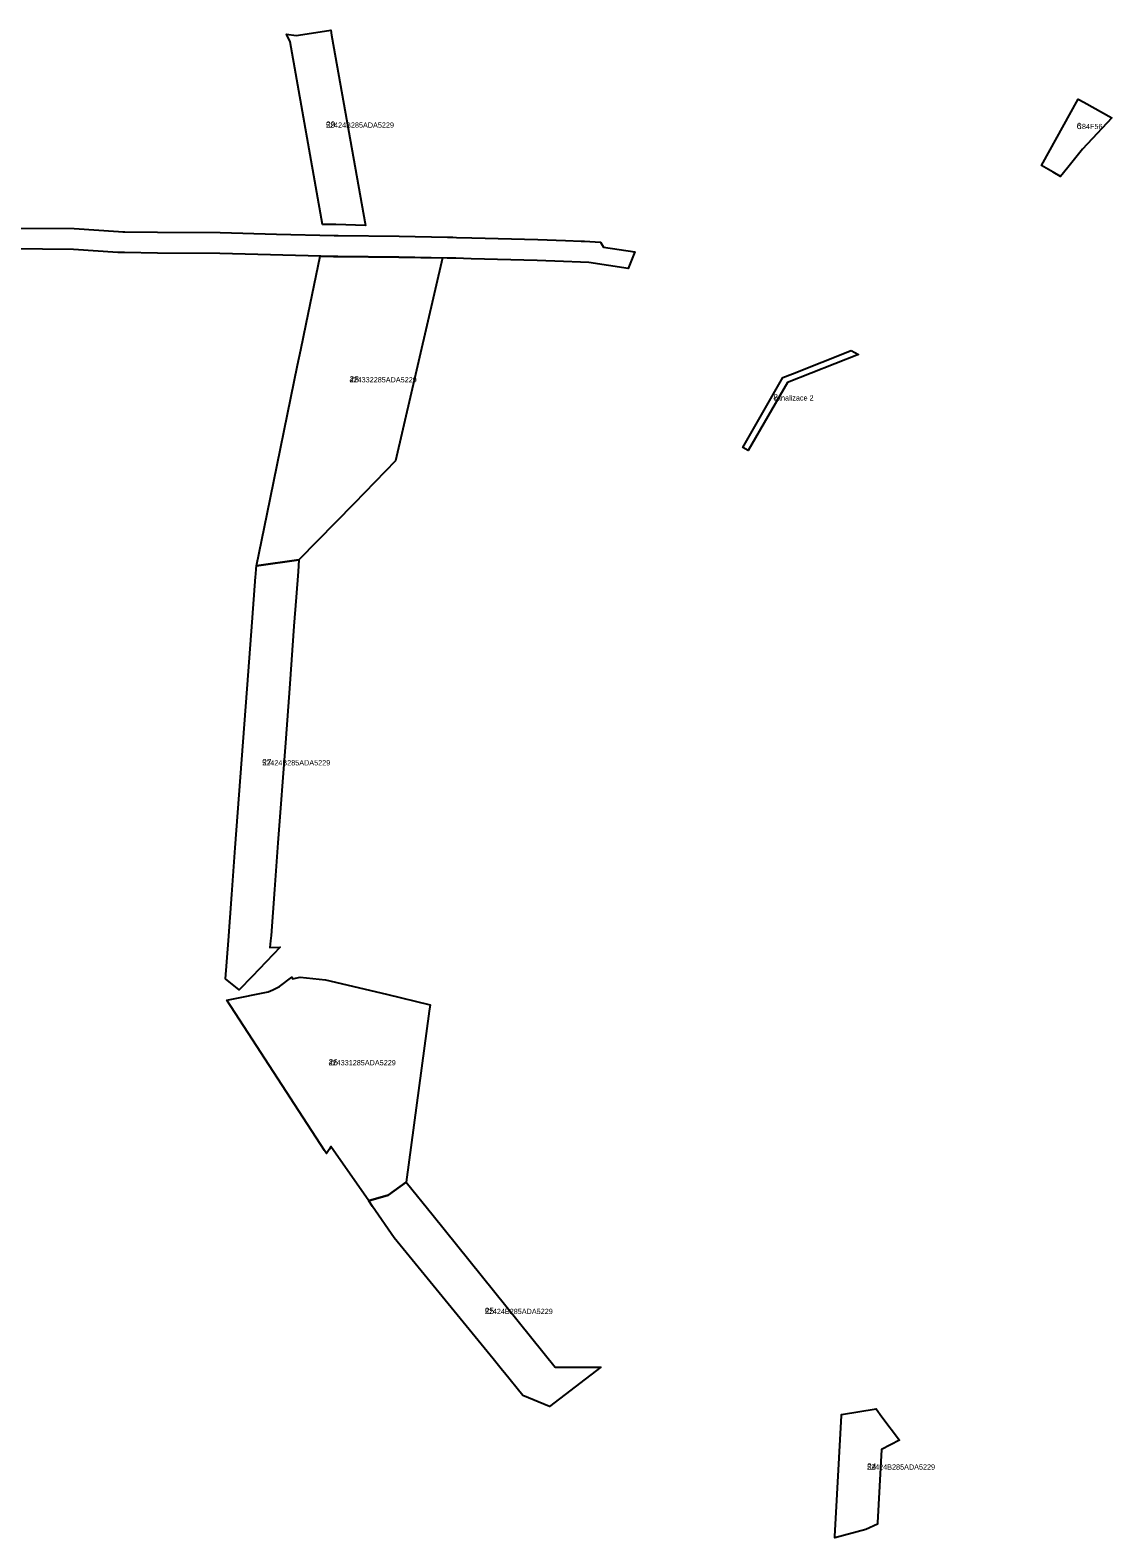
# Model space of a CAD drawing. Extents: x -540086 to -538022, y -1162553 to -1159940.
# Drawn here: x -539054 to -538022, y -1162553 to -1161115 of the extents above; entities that cross this region are included whole.
import ezdxf

# ---------------------------------------------------------------- set-up
doc = ezdxf.new("R2010")
doc.units = 0
for name, color, linetype in [('96120023', 7, 'Continuous'), ('96140023', 7, 'Continuous'), ('ID_VPO', 7, 'Continuous'), ('ID_VPS', 7, 'Continuous')]:
    doc.layers.add(name, color=color, linetype=linetype)

msp = doc.modelspace()

# ---------------------------------------------------------------- linework, layer by layer
at = {"layer": '96120023'}
for points in [[(-538063.9, -1161245.9), (-538070.9, -1161254.5), (-538078.1, -1161250.3), (-538089, -1161244.1), (-538054.2, -1161180.6), (-538048.7, -1161183.6), (-538022, -1161198.5), (-538049.9, -1161228.5)], [(-538270.8, -1161420.6), (-538263.8, -1161424.2), (-538331.5, -1161451), (-538368.8, -1161515.9), (-538374, -1161512.9), (-538335.7, -1161446.2), (-538335.7, -1161446.2), (-538326.7, -1161442.6)]]:
    msp.add_lwpolyline(points, close=True, dxfattribs=at)
msp.add_lwpolyline([(-539073, -1161303.6), (-539011.9, -1161304.2), (-538969.5, -1161307), (-538965.6, -1161307.1), (-538963.6, -1161307.1), (-538932.3, -1161307.5), (-538872.6, -1161308), (-538818.8, -1161309.4), (-538763.9, -1161310.7), (-538759.9, -1161310.9), (-538702, -1161311.5), (-538655.9, -1161312.3), (-538650.6, -1161312.4), (-538647.1, -1161312.5), (-538632.6, -1161312.9), (-538569.5, -1161314.7), (-538543.2, -1161315.4), (-538528.1, -1161316.2), (-538525.1, -1161316.3), (-538509.9, -1161317), (-538506.8, -1161321.8), (-538477.1, -1161326.2), (-538483.5, -1161342.2), (-538521, -1161336.5), (-538529, -1161336.1), (-538545, -1161335.4), (-538570.1, -1161334.7), (-538633.2, -1161332.9), (-538647.7, -1161332.5), (-538656.2, -1161332.3), (-538702.3, -1161331.5), (-538760.4, -1161330.8), (-538764.6, -1161330.7), (-538872.9, -1161328), (-538932.5, -1161327.5), (-538963.9, -1161327.1), (-538970.4, -1161327), (-539012.7, -1161324.2), (-539071.6, -1161323.6)], dxfattribs=at)
at = {"layer": '96140023'}
for points in [[(-538762.2, -1161300.4), (-538775, -1161300.2), (-538805.7, -1161126), (-538809.4, -1161118.5), (-538800.1, -1161120), (-538777.3, -1161116.4), (-538767.2, -1161114.8), (-538766.4, -1161119.7), (-538734, -1161301.3)], [(-538838, -1161625.8), (-538827.8, -1161576.4), (-538798.7, -1161434.4), (-538795.7, -1161419.9), (-538790.6, -1161394.9), (-538777.3, -1161330.4), (-538764.6, -1161330.7), (-538760.4, -1161330.8), (-538702.3, -1161331.5), (-538660.5, -1161332.2), (-538705.3, -1161525.9), (-538744.9, -1161566.5), (-538797.5, -1161620.3)], [(-538838.2, -1161628.7), (-538838, -1161625.8), (-538797.5, -1161620.3), (-538798.3, -1161631.5), (-538800.1, -1161655.9), (-538802.2, -1161683.6), (-538806.3, -1161738.5), (-538810.4, -1161794.8), (-538817.5, -1161890.2), (-538820.8, -1161934.9), (-538824.1, -1161978.8), (-538824.5, -1161983.9), (-538825.3, -1161990.1), (-538815.4, -1161989.8), (-538842, -1162017.7), (-538854.4, -1162030.6), (-538867.5, -1162019.9), (-538864.8, -1161983.6), (-538861.5, -1161939.7), (-538858.2, -1161895), (-538846.8, -1161743.2), (-538842.7, -1161688.3), (-538838.8, -1161636.3), (-538838.6, -1161634)], [(-538713.9, -1162034.8), (-538672.3, -1162044.8), (-538673.1, -1162051), (-538695.1, -1162214.1), (-538712.3, -1162226.5), (-538729, -1162231.4), (-538730.9, -1162232), (-538766.9, -1162179.9), (-538768.8, -1162182.8), (-538771.3, -1162186.7), (-538773.1, -1162183.9), (-538866.2, -1162040.4), (-538863.1, -1162039.8), (-538826.9, -1162032.5), (-538822.4, -1162030.5), (-538816, -1162027.5), (-538804.3, -1162018.4), (-538803.6, -1162020.1), (-538796.4, -1162018.5), (-538772, -1162020.9)], [(-538730.9, -1162232), (-538729, -1162231.4), (-538712.3, -1162226.5), (-538695.1, -1162214.1), (-538669.3, -1162246), (-538552.9, -1162390.5), (-538509.5, -1162390.5), (-538558.5, -1162428.2), (-538583.9, -1162417.5), (-538601.5, -1162395.9), (-538603.2, -1162393.8), (-538612.1, -1162382.8), (-538706.6, -1162267.1), (-538727.3, -1162237.2)], [(-538279.9, -1162436.7), (-538279.8, -1162435.8), (-538246.9, -1162430.4), (-538241.3, -1162437.9), (-538224.6, -1162460.2), (-538241.8, -1162469.1), (-538245.6, -1162539), (-538245.6, -1162540.4), (-538256.7, -1162545.4), (-538286.4, -1162553.5), (-538286.3, -1162552.2)]]:
    msp.add_lwpolyline(points, close=True, dxfattribs=at)

# ---------------------------------------------------------------- texts
at = {"layer": '96120023'}
for s, p in [('C84F56', (-538055.5, -1161209.2)), ('kanalizace 2', (-538344.9, -1161468.2))]:
    msp.add_text(s, height=5, rotation=360, dxfattribs=at).set_placement(p)
at = {"layer": '96140023'}
for s, rotation, p in [('52424B285ADA5229', 360, (-538771.7, -1161207.9)), ('424332285ADA5229', 0, (-538749.2, -1161450.9)), ('424331285ADA5229', 0, (-538769.2, -1162102.6)), ('52424B285ADA5229', 0, (-538620.2, -1162339.9)), ('52424B285ADA5229', 0, (-538255.5, -1162488.4))]:
    msp.add_text(s, height=5, rotation=rotation, dxfattribs=at).set_placement(p)
msp.add_text('52424B285ADA5229', height=5, dxfattribs=at).set_placement((-538832.5, -1161816.4))
at = {"layer": 'ID_VPO'}
for s, rotation, p in [('29', 0, (-538771.7, -1161207.9)), ('28', 360, (-538749.2, -1161450.9)), ('27', 0, (-538832.5, -1161816.4)), ('26', 0, (-538769.2, -1162102.6)), ('25', 0, (-538620.2, -1162339.9)), ('24', 0, (-538255.5, -1162488.4))]:
    msp.add_text(s, height=6, rotation=rotation, dxfattribs=at).set_placement(p)
at = {"layer": 'ID_VPS'}
for s, rotation, p in [('6', 0, (-538055.5, -1161209.2)), ('8', 360, (-538344.9, -1161468.2))]:
    msp.add_text(s, height=6, rotation=rotation, dxfattribs=at).set_placement(p)

doc.saveas('drawing.dxf')
